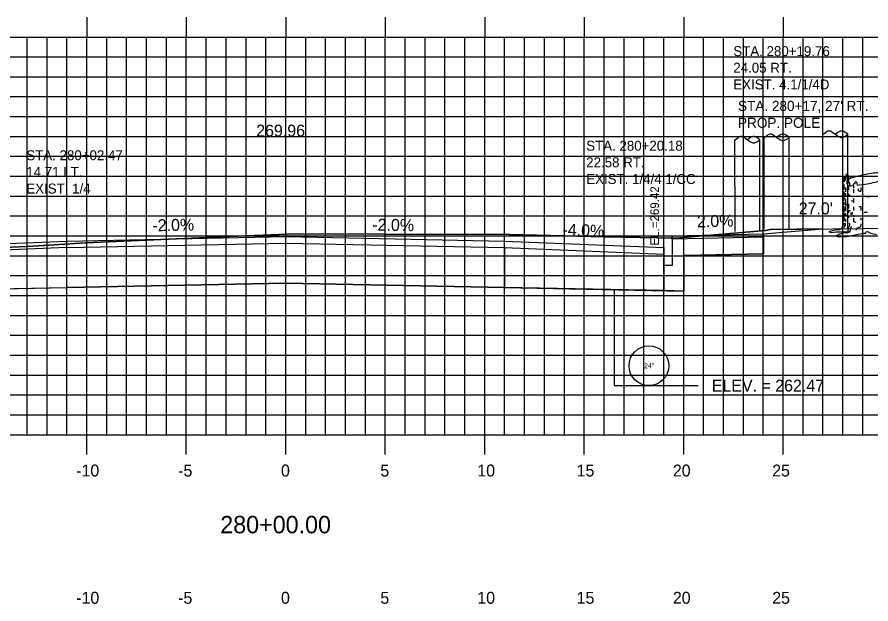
# Model space of a CAD drawing. Extents: x 855121 to 855291, y 366268 to 366378.
# Drawn here: x 855190.94 to 855233.85, y 366298.73 to 366328.24 of the extents above; entities that cross this region are included whole.
import ezdxf

# ---------------------------------------------------------------- set-up
doc = ezdxf.new("R2010")
doc.units = 0
for name, color, linetype in [('ANNOTATION', 7, 'Continuous'), ('D_Curb_Type_1_Rt', 7, 'Continuous'), ('D_Roadway_Centerline', 7, 'Continuous'), ('D_Roadway_Centerline_Text', 7, 'Continuous'), ('D_Roadway_Edge_Shoulder', 7, 'Continuous'), ('D_Roadway_FinishedGrade', 7, 'Continuous'), ('D_Roadway_Sidewalks_Paved', 7, 'Continuous'), ('D_Roadway_SubGrade', 7, 'Continuous'), ('D_Text_Monospaced', 7, 'Continuous'), ('D_Text_Standard', 7, 'Continuous'), ('D_Utilities_Pole_Joint', 7, 'Continuous'), ('D_Utilities_Text', 7, 'Continuous'), ('H_V ANNOTATION', 7, 'Continuous'), ('JUNK COM EXC', 7, 'Continuous'), ('junk strct exc', 7, 'Continuous'), ('MAJOR', 7, 'Continuous'), ('MINOR', 7, 'Continuous'), ('PDRAIN', 7, 'Continuous'), ('S_Roadway_Centerline', 7, 'Continuous'), ('S_Trees_Decid_Pay', 7, 'Continuous'), ('S_Utilities_Pole_Power', 7, 'Continuous')]:
    doc.layers.add(name, color=color, linetype=linetype)

msp = doc.modelspace()

# ---------------------------------------------------------------- linework, layer by layer
at = {"layer": 'D_Curb_Type_1_Rt'}
msp.add_lwpolyline([(855223.859, 366317.24), (855223.859, 366315.74), (855223.442, 366315.74), (855223.442, 366317.24)], close=True, dxfattribs=at)
at = {"layer": 'D_Roadway_Centerline'}
msp.add_lwpolyline([(855193.442, 366316.977), (855204.442, 366317.197), (855215.442, 366316.977)], dxfattribs=at)
at = {"layer": 'D_Roadway_Edge_Shoulder'}
msp.add_line((855223.442, 366316.656), (855223.442, 366316.323), dxfattribs=at)
msp.add_lwpolyline([(855185.442, 366316.657), (855193.442, 366316.977), (855204.442, 366317.197), (855215.442, 366316.977), (855223.442, 366316.656)], dxfattribs=at)
at = {"layer": 'D_Roadway_FinishedGrade'}
msp.add_line((855228.448, 366317.331), (855231.442, 366317.59), dxfattribs=at)
at = {"layer": 'D_Roadway_Sidewalks_Paved'}
msp.add_lwpolyline([(855223.859, 366317.239), (855228.448, 366317.331), (855228.448, 366317.164), (855223.859, 366317.072)], close=True, dxfattribs=at)
at = {"layer": 'D_Roadway_SubGrade'}
msp.add_lwpolyline([(855228.448, 366317.164), (855228.448, 366316.331), (855224.443, 366316.251), (855224.443, 366314.463), (855223.442, 366314.483)], dxfattribs=at)
for points in [[(855193.442, 366314.643), (855193.442, 366316.643), (855204.442, 366316.863), (855215.442, 366316.643), (855215.442, 366314.643), (855204.442, 366314.863)], [(855193.442, 366316.643), (855185.442, 366316.323), (855185.442, 366314.483), (855193.442, 366314.643)], [(855215.442, 366316.643), (855223.442, 366316.323), (855223.442, 366314.483), (855215.442, 366314.643)]]:
    msp.add_lwpolyline(points, close=True, dxfattribs=at)
at = {"layer": 'D_Text_Standard'}
msp.add_lwpolyline([(855224.443, 366309.706), (855224.493, 366309.706), (855225.173, 366309.706)], dxfattribs=at)
at = {"layer": 'D_Utilities_Pole_Joint'}
for p, q in [((855231.442, 366322.348), (855231.598, 366322.458)), ((855231.442, 366317.59), (855231.442, 366322.348)), ((855231.91, 366322.458), (855232.067, 366322.348)), ((855232.223, 366322.458), (855232.067, 366322.348)), ((855232.067, 366322.348), (855232.223, 366322.237)), ((855232.692, 366322.348), (855232.536, 366322.458)), ((855232.536, 366322.237), (855232.692, 366322.348)), ((855232.692, 366317.59), (855232.692, 366322.348))]:
    msp.add_line(p, q, dxfattribs=at)
for centre, start, end in [((855231.754, 366322.237), 90, 125.2644), ((855231.754, 366322.237), 54.7356, 90), ((855232.379, 366322.237), 90, 125.2644), ((855232.379, 366322.237), 54.7356, 90), ((855232.379, 366322.458), 234.7356, 270), ((855232.379, 366322.458), 270, 305.2644)]:
    msp.add_arc(centre, 0.271, start, end, dxfattribs=at)
at = {"layer": 'JUNK COM EXC'}
msp.add_lwpolyline([(855184.442, 366314.463), (855193.442, 366314.643), (855204.442, 366314.863), (855215.442, 366314.643), (855224.443, 366314.463), (855224.443, 366316.251), (855228.448, 366316.331), (855228.448, 366317.331), (855231.442, 366317.59), (855228.791, 366317.564), (855228.553, 366317.499), (855224.022, 366317.119), (855220.47, 366317.191), (855215.662, 366317.297), (855209.434, 366317.327), (855204.941, 366317.345), (855201.614, 366317.202), (855194.375, 366316.881), (855191.742, 366316.723), (855188.805, 366316.582)], dxfattribs=at)
at = {"layer": 'junk strct exc'}
msp.add_lwpolyline([(855220.943, 366314.533), (855220.943, 366309.706), (855224.443, 366309.706), (855224.443, 366314.463)], close=True, dxfattribs=at)
at = {"layer": 'MAJOR'}
for p, q in [((855194.442, 366328.238), (855194.442, 366327.236)), ((855199.442, 366328.238), (855199.442, 366327.236)), ((855204.442, 366328.238), (855204.442, 366327.236)), ((855209.442, 366328.238), (855209.442, 366327.236)), ((855214.442, 366328.238), (855214.442, 366327.236)), ((855219.442, 366328.238), (855219.442, 366327.236)), ((855224.442, 366328.238), (855224.442, 366327.236)), ((855229.442, 366328.238), (855229.442, 366327.236)), ((855134.442, 366327.236), (855274.442, 366327.236)), ((855134.442, 366327.236), (855274.442, 366327.236)), ((855194.442, 366307.236), (855194.442, 366327.236)), ((855199.442, 366307.236), (855199.442, 366327.236)), ((855204.442, 366307.236), (855204.442, 366327.236)), ((855209.442, 366307.236), (855209.442, 366327.236)), ((855214.442, 366307.236), (855214.442, 366327.236)), ((855219.442, 366307.236), (855219.442, 366327.236)), ((855224.442, 366307.236), (855224.442, 366327.236)), ((855229.442, 366307.236), (855229.442, 366327.236)), ((855134.442, 366322.236), (855274.442, 366322.236)), ((855134.442, 366317.236), (855274.442, 366317.236)), ((855134.442, 366312.236), (855274.442, 366312.236)), ((855134.442, 366307.236), (855274.442, 366307.236)), ((855134.442, 366307.236), (855274.442, 366307.236)), ((855194.442, 366306.234), (855194.442, 366307.236)), ((855199.442, 366306.234), (855199.442, 366307.236)), ((855204.442, 366306.234), (855204.442, 366307.236)), ((855209.442, 366306.234), (855209.442, 366307.236)), ((855214.442, 366306.234), (855214.442, 366307.236)), ((855219.442, 366306.234), (855219.442, 366307.236)), ((855224.442, 366306.234), (855224.442, 366307.236)), ((855229.442, 366306.234), (855229.442, 366307.236))]:
    msp.add_line(p, q, dxfattribs=at)
at = {"layer": 'MINOR'}
for p, q in [((855191.442, 366307.236), (855191.442, 366327.236)), ((855192.442, 366307.236), (855192.442, 366327.236)), ((855193.442, 366307.236), (855193.442, 366327.236)), ((855195.442, 366307.236), (855195.442, 366327.236)), ((855196.442, 366307.236), (855196.442, 366327.236)), ((855197.442, 366307.236), (855197.442, 366327.236)), ((855198.442, 366307.236), (855198.442, 366327.236)), ((855200.442, 366307.236), (855200.442, 366327.236)), ((855201.442, 366307.236), (855201.442, 366327.236)), ((855202.442, 366307.236), (855202.442, 366327.236)), ((855203.442, 366307.236), (855203.442, 366327.236)), ((855205.442, 366307.236), (855205.442, 366327.236)), ((855206.442, 366307.236), (855206.442, 366327.236)), ((855207.442, 366307.236), (855207.442, 366327.236)), ((855208.442, 366307.236), (855208.442, 366327.236)), ((855210.442, 366307.236), (855210.442, 366327.236)), ((855211.442, 366307.236), (855211.442, 366327.236)), ((855212.442, 366307.236), (855212.442, 366327.236)), ((855213.442, 366307.236), (855213.442, 366327.236)), ((855215.442, 366307.236), (855215.442, 366327.236)), ((855216.442, 366307.236), (855216.442, 366327.236)), ((855217.442, 366307.236), (855217.442, 366327.236)), ((855218.442, 366307.236), (855218.442, 366327.236)), ((855220.442, 366307.236), (855220.442, 366327.236)), ((855221.442, 366307.236), (855221.442, 366327.236)), ((855222.442, 366307.236), (855222.442, 366327.236)), ((855223.442, 366307.236), (855223.442, 366327.236)), ((855225.442, 366307.236), (855225.442, 366327.236)), ((855226.442, 366307.236), (855226.442, 366327.236)), ((855227.442, 366307.236), (855227.442, 366327.236)), ((855228.442, 366307.236), (855228.442, 366327.236)), ((855230.442, 366307.236), (855230.442, 366327.236)), ((855231.442, 366307.236), (855231.442, 366327.236)), ((855232.442, 366307.236), (855232.442, 366327.236)), ((855233.442, 366307.236), (855233.442, 366327.236)), ((855134.442, 366326.236), (855274.442, 366326.236)), ((855134.442, 366325.236), (855274.442, 366325.236)), ((855134.442, 366324.236), (855274.442, 366324.236)), ((855134.442, 366323.236), (855274.442, 366323.236)), ((855134.442, 366321.236), (855274.442, 366321.236)), ((855134.442, 366320.236), (855274.442, 366320.236)), ((855134.442, 366319.236), (855274.442, 366319.236)), ((855134.442, 366318.236), (855274.442, 366318.236)), ((855134.442, 366316.236), (855274.442, 366316.236)), ((855134.442, 366315.236), (855274.442, 366315.236)), ((855134.442, 366314.236), (855274.442, 366314.236)), ((855134.442, 366313.236), (855274.442, 366313.236)), ((855134.442, 366311.236), (855274.442, 366311.236)), ((855134.442, 366310.236), (855274.442, 366310.236)), ((855134.442, 366309.236), (855274.442, 366309.236)), ((855134.442, 366308.236), (855274.442, 366308.236))]:
    msp.add_line(p, q, dxfattribs=at)
at = {"layer": 'PDRAIN'}
msp.add_lwpolyline([(855220.943, 366314.533), (855220.943, 366309.706), (855224.443, 366309.706), (855224.443, 366314.463)], dxfattribs=at)
msp.add_circle((855222.693, 366310.706), 1, dxfattribs=at)
at = {"layer": 'S_Roadway_Centerline'}
msp.add_lwpolyline([(855146.902, 366317.671), (855147.024, 366317.289), (855147.254, 366316.598), (855147.777, 366316.658), (855148.726, 366316.597), (855149.663, 366316.602), (855156.3, 366316.664), (855158.414, 366316.671), (855184.618, 366316.907), (855186.136, 366316.886), (855188.09, 366316.761), (855188.288, 366316.664), (855188.805, 366316.582), (855191.742, 366316.723), (855194.375, 366316.881), (855201.614, 366317.202), (855204.941, 366317.345), (855209.434, 366317.327), (855215.662, 366317.297), (855220.47, 366317.191), (855224.022, 366317.119), (855228.553, 366317.499), (855228.791, 366317.564), (855239.683, 366317.672)], dxfattribs=at)
at = {"layer": 'S_Trees_Decid_Pay'}
for p, q in [((855232.487, 366319.811), (855232.487, 366319.557)), ((855232.637, 366320.011), (855232.637, 366319.837)), ((855232.721, 366319.763), (855232.721, 366319.558)), ((855232.983, 366319.765), (855232.983, 366319.645)), ((855232.487, 366319.459), (855232.487, 366318.99)), ((855232.573, 366319.665), (855232.573, 366319.454)), ((855232.573, 366319.388), (855232.573, 366319.24)), ((855232.721, 366319.351), (855232.721, 366319.196)), ((855232.983, 366319.593), (855232.983, 366319.408)), ((855233.221, 366319.493), (855233.226, 366319.6)), ((855233.347, 366319.665), (855233.347, 366319.486)), ((855232.487, 366318.939), (855232.487, 366318.805)), ((855232.573, 366319.062), (855232.573, 366318.762)), ((855232.983, 366319.122), (855232.983, 366318.894)), ((855232.487, 366318.747), (855232.487, 366318.422)), ((855232.573, 366318.725), (855232.573, 366318.482)), ((855232.721, 366318.833), (855232.721, 366318.614)), ((855232.721, 366318.514), (855232.721, 366318.393)), ((855232.983, 366318.696), (855232.983, 366318.511)), ((855233.347, 366318.707), (855233.347, 366318.511)), ((855232.487, 366318.393), (855232.487, 366317.973)), ((855232.573, 366318.371), (855232.573, 366318.23)), ((855232.573, 366318.099), (855232.573, 366317.942)), ((855232.721, 366318.242), (855232.721, 366318.144)), ((855232.983, 366318.276), (855232.983, 366318.199)), ((855232.983, 366318.122), (855232.983, 366317.948)), ((855233.347, 366318.127), (855233.347, 366318.024)), ((855232.491, 366317.87), (855232.476, 366317.753))]:
    msp.add_line(p, q, dxfattribs=at)
for points in [[(855232.793, 366319.758), (855232.785, 366319.902), (855232.74, 366319.894), (855232.725, 366320.269), (855232.631, 366320.277), (855232.616, 366320.357), (855232.579, 366320.02), (855232.534, 366320.114), (855232.513, 366319.96), (855232.437, 366320.085), (855232.443, 366319.896)], [(855232.437, 366320.085), (855232.483, 366320.108), (855232.505, 366320.174), (855232.557, 366320.197), (855232.59, 366320.122)], [(855232.815, 366320.124), (855232.836, 366320.232), (855232.968, 366320.263), (855232.975, 366320.175)], [(855232.437, 366320.085), (855232.437, 366317.948), (855232.416, 366317.807), (855232.41, 366317.681), (855232.367, 366317.594), (855232.275, 366317.545), (855232.139, 366317.545), (855231.895, 366317.489), (855231.729, 366317.44), (855231.871, 366317.409), (855232.108, 366317.446), (855232.318, 366317.434), (855232.579, 366317.44), (855232.703, 366317.458), (855232.733, 366317.415), (855232.796, 366317.458), (855232.697, 366317.391), (855232.462, 366317.366), (855232.231, 366317.304), (855232.101, 366317.234), (855232.2, 366317.19), (855232.622, 366317.209), (855232.901, 366317.253), (855233.199, 366317.329), (855233.485, 366317.366), (855233.59, 366317.366), (855233.609, 366317.446), (855233.677, 366317.452), (855233.844, 366317.366), (855234.13, 366317.31)], [(855232.954, 366319.763), (855232.991, 366319.866), (855233.057, 366319.872), (855233.057, 366319.954), (855233.131, 366319.96), (855233.156, 366319.78)], [(855232.845, 366318.393), (855232.836, 366318.319), (855232.91, 366318.313), (855232.925, 366318.43)], [(855232.557, 366317.878), (855232.55, 366317.753), (855232.468, 366317.658)], [(855232.703, 366317.458), (855232.721, 366317.637), (855232.783, 366317.774), (855232.777, 366317.874)], [(855232.894, 366317.706), (855232.82, 366317.637), (855232.802, 366317.539), (855232.796, 366317.458)], [(855233.345, 366317.841), (855233.328, 366317.687), (855233.131, 366317.606), (855233.086, 366317.503)]]:
    msp.add_lwpolyline(points, dxfattribs=at)
for centre, radius, start, end in [((855234.727, 366314.304), 6.126, 100.7779, 107.8613), ((855234.727, 366314.304), 6.126, 93.6944, 100.7779), ((855232.485, 366319.717), 0.0476, 180, 191.6815), ((855233.246, 366318.898), 1.299, 107.8613, 113.3069), ((855232.835, 366321.057), 1.299, 268.1289, 273.6944), ((855232.524, 366325.873), 6.126, 273.6944, 274.0246), ((855232.524, 366325.873), 6.126, 275.9147, 280.7779), ((855232.524, 366325.873), 6.126, 280.7779, 287.8613), ((855232.492, 366319.719), 0.0554, 191.6815, 202.5), ((855232.502, 366319.723), 0.0657, 202.5, 215.1737), ((855232.537, 366319.748), 0.109, 215.1737, 225), ((855232.578, 366319.788), 0.166, 225, 239.1924), ((855232.578, 366319.525), 0.166, 237.0378, 239.1924), ((855232.741, 366319.798), 0.484, 239.1924, 247.5), ((855233.05, 366320.544), 1.292, 247.5, 248.3537), ((855233.05, 366320.807), 1.292, 250.6119, 255.2856), ((855233.05, 366320.544), 1.292, 255.2856, 259.2632), ((855233.626, 366325.395), 5.916, 266.0776, 267.3043), ((855232.485, 366319.196), 0.0476, 180, 191.6815), ((855232.485, 366318.939), 0.0476, 180, 191.6815), ((855232.492, 366319.198), 0.0554, 191.6815, 202.5), ((855232.492, 366318.94), 0.0554, 191.6815, 202.5), ((855232.502, 366319.202), 0.0657, 202.5, 215.1737), ((855232.502, 366318.944), 0.0657, 202.5, 215.1737), ((855232.537, 366319.227), 0.109, 215.1737, 225), ((855232.537, 366318.969), 0.109, 215.1737, 225), ((855232.578, 366319.267), 0.166, 225, 239.1924), ((855232.578, 366319.01), 0.166, 225, 239.1924), ((855232.741, 366319.54), 0.484, 239.1924, 245.7725), ((855233.05, 366320.286), 1.292, 247.5, 248.4842), ((855233.05, 366320.286), 1.292, 261.8726, 262.8454), ((855233.626, 366324.874), 5.916, 262.8454, 263.7595), ((855233.626, 366325.132), 5.916, 270.1162, 271.7708), ((855232.485, 366318.673), 0.0476, 180, 191.6815), ((855232.492, 366318.675), 0.0554, 191.6815, 202.5), ((855232.502, 366318.679), 0.0657, 202.5, 215.1737), ((855232.537, 366318.704), 0.109, 215.1737, 225), ((855232.578, 366318.744), 0.166, 225, 239.1924), ((855232.741, 366319.017), 0.484, 239.1924, 247.5), ((855233.05, 366320.029), 1.292, 247.5, 251.799), ((855233.05, 366319.764), 1.292, 247.5, 248.3537), ((855233.05, 366319.764), 1.292, 255.2856, 259.2463), ((855233.626, 366324.617), 5.916, 266.2721, 267.3043), ((855233.626, 366324.351), 5.916, 268.9207, 270), ((855233.626, 366324.351), 5.916, 270, 270.2757), ((855232.485, 366318.144), 0.0476, 180, 191.6815), ((855232.492, 366318.146), 0.0554, 191.6815, 202.5), ((855232.502, 366318.15), 0.0657, 202.5, 215.1737), ((855232.537, 366318.175), 0.109, 215.1737, 225), ((855232.578, 366318.215), 0.166, 225, 239.1924), ((855232.741, 366318.488), 0.484, 239.1924, 247.5), ((855232.741, 366318.745), 0.484, 242.734, 247.5), ((855233.05, 366319.234), 1.292, 247.5, 248.3537), ((855233.05, 366319.492), 1.292, 251.3664, 255.2856), ((855233.626, 366323.822), 5.916, 263.7831, 264.7656)]:
    msp.add_arc(centre, radius, start, end, dxfattribs=at)
at = {"layer": 'S_Utilities_Pole_Power'}
for p, q in [((855228.49, 366322.19), (855228.646, 366322.3)), ((855228.959, 366322.3), (855229.115, 366322.19)), ((855229.272, 366322.3), (855229.115, 366322.19)), ((855229.74, 366322.19), (855229.584, 366322.3)), ((855227.02, 366317.453), (855227.017, 366322.072)), ((855227.02, 366322.072), (855227.176, 366322.183)), ((855227.489, 366322.183), (855227.645, 366322.072)), ((855227.802, 366322.183), (855227.645, 366322.072)), ((855227.645, 366322.072), (855227.802, 366321.961)), ((855228.27, 366322.072), (855228.114, 366322.183)), ((855228.114, 366321.961), (855228.27, 366322.072)), ((855228.27, 366317.453), (855228.267, 366322.072)), ((855228.49, 366317.571), (855228.487, 366322.19)), ((855229.115, 366322.19), (855229.272, 366322.079)), ((855229.584, 366322.079), (855229.74, 366322.19)), ((855229.74, 366317.571), (855229.737, 366322.19))]:
    msp.add_line(p, q, dxfattribs=at)
for centre, start, end in [((855228.802, 366322.08), 90, 125.2644), ((855228.802, 366322.08), 54.7356, 90), ((855229.427, 366322.08), 90, 125.2644), ((855229.427, 366322.08), 54.7356, 90), ((855227.332, 366321.962), 90, 125.2644), ((855227.332, 366321.962), 54.7356, 90), ((855227.957, 366321.962), 90, 125.2644), ((855227.957, 366322.183), 234.7356, 270), ((855227.957, 366321.962), 54.7356, 90), ((855227.957, 366322.183), 270, 305.2644), ((855229.427, 366322.3), 234.7356, 270), ((855229.427, 366322.3), 270, 305.2644)]:
    msp.add_arc(centre, 0.271, start, end, dxfattribs=at)

# ---------------------------------------------------------------- texts
at = {"layer": 'ANNOTATION'}
for s, rotation, p in [('-2.0%', 1.1458, (855197.745, 366317.463)), ('-2.0%', 358.8542, (855208.785, 366317.51)), ('2.0%', 1.1485, (855225.115, 366317.665)), ('-4.0%', 357.7093, (855218.341, 366317.261))]:
    msp.add_text(s, height=0.6, rotation=rotation, dxfattribs=at).set_placement(p)
at = {"layer": 'D_Roadway_Centerline_Text'}
msp.add_text('269.96', height=0.6, dxfattribs=at).set_placement((855202.954, 366322.229))
at = {"layer": 'D_Text_Monospaced'}
for s, height, p in [('STA. 280+19.76', 0.49998, (855226.934, 366326.275)), ('24.05 RT.', 0.5, (855226.934, 366325.441)), ('EXIST. 4.1/1/4D', 0.49998, (855226.934, 366324.601)), ('STA. 280+20.18', 0.49998, (855219.541, 366321.519)), ('STA. 280+02.47', 0.49998, (855191.4, 366321.04)), ('22.58 RT.', 0.5, (855219.541, 366320.685)), ('14.71 LT.', 0.5, (855191.4, 366320.206)), ('EXIST. 1/4/4.1/CC', 0.49998, (855219.541, 366319.845)), ('EXIST. 1/4', 0.5, (855191.4, 366319.366))]:
    msp.add_text(s, height=height, dxfattribs=at).set_placement(p)
at = {"layer": 'D_Text_Standard'}
msp.add_text(' EL.=269.42', height=0.4335, rotation=90, dxfattribs=at).set_placement((855223.196, 366316.588))
for s, p in [("27.0'", (855230.222, 366318.317)), ('ELEV. = 262.47', (855225.853, 366309.406))]:
    msp.add_text(s, height=0.6, dxfattribs=at).set_placement(p)
at = {"layer": 'D_Utilities_Text'}
for s, p in [("STA. 280+17, 27' RT.", (855227.169, 366323.516)), ('PROP. POLE', (855227.169, 366322.666))]:
    msp.add_text(s, height=0.51, dxfattribs=at).set_placement(p)
at = {"layer": 'H_V ANNOTATION'}
for s, height, p in [('-10', 0.6, (855193.907, 366305.136)), ('-5', 0.6, (855199.032, 366305.136)), ('0', 0.6, (855204.201, 366305.136)), ('5', 0.6, (855209.193, 366305.136)), ('10', 0.6, (855214.067, 366305.136)), ('15', 0.6, (855219.059, 366305.136)), ('20', 0.6, (855223.896, 366305.136)), ('25', 0.6, (855228.888, 366305.136)), ('280+00.00', 0.875, (855201.149, 366302.28)), ('-10', 0.6, (855193.907, 366298.736)), ('-5', 0.6, (855199.032, 366298.736)), ('0', 0.6, (855204.201, 366298.736)), ('5', 0.6, (855209.193, 366298.736)), ('10', 0.6, (855214.067, 366298.736)), ('15', 0.6, (855219.059, 366298.736)), ('20', 0.6, (855223.896, 366298.736)), ('25', 0.6, (855228.888, 366298.736))]:
    msp.add_text(s, height=height, dxfattribs=at).set_placement(p)
at = {"layer": 'PDRAIN'}
msp.add_text('24"', height=0.25, dxfattribs=at).set_placement((855222.451, 366310.581))
at = {"layer": 'S_Roadway_Centerline'}
for s, p in [('C', (855204.935, 366317.345)), ('L', (855204.941, 366317.338))]:
    msp.add_text(s, height=0.0146, dxfattribs=at).set_placement(p)

doc.saveas('drawing.dxf')
